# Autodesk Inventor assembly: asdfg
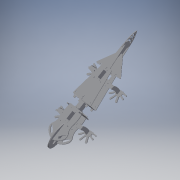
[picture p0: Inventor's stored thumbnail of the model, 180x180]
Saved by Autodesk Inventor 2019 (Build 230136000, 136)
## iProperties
Created: 2020-02
Part Number: asdfg
Document SubType Name: Assembly
Designer: shivu
Author: shivu
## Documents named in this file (10)
- C:\Users\shivu\Desktop\exploration\asdfg.iam
- C:\Users\shivu\Desktop\exploration\connector.ipt
- C:\Users\shivu\Downloads\11.ipt
- C:\Users\shivu\Desktop\exploration\final_upper.ipt
- C:\Users\shivu\Desktop\end part.iam
- C:\Users\shivu\Desktop\exploration\face.ipt
- C:\Users\shivu\Desktop\exploration\head upper.ipt
- C:\Users\shivu\Desktop\exploration\part99.ipt
- C:\Users\shivu\Desktop\exploration\part1000.ipt
- C:\Users\shivu\Desktop\exploration\servo.ipt
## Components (14 placed, 9 different names)
1. 11:1 — Rigid:16, Rigid:17, Rigid:26
2. connector:1 — Rotational:1, Cylindrical:1
3. final_upper:1 — Rigid:17, Rotational:1, Rigid:24
4. final_upper:2 — Rigid:16
5. end part:1 [sub-assembly] — Cylindrical:1
6. part99:1 — Rotational:3, Rigid:27, Rigid:28
7. part1000:2 — Rotational:2
8. servo:3 — Rigid:26, Rotational:3
9. servo:4 — Rigid:24, Rotational:2
10. head upper:1 — Rigid:27, Rigid:29, Rigid:30
11. head upper:2 — Rigid:28
12. face:1 — Rigid:29
13. servo:5 — Rigid:30, Rigid:31
14. part1000:3 — Rigid:31
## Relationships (13: WeldJoint 9, RevoluteJoint 3, CylindricalJoint 1)
- Rigid:16 [WeldJoint]: 11:1 ↔ final_upper:2
- Rigid:17 [WeldJoint]: 11:1 ↔ final_upper:1
- Rotational:1 [RevoluteJoint]: connector:1 ↔ final_upper:1
- Cylindrical:1: connector:1 ↔ end part:1
- Rigid:24 [WeldJoint]: final_upper:1 ↔ servo:4
- Rotational:2 [RevoluteJoint]: part1000:2 ↔ servo:4
- Rigid:26 [WeldJoint]: 11:1 ↔ servo:3
- Rotational:3 [RevoluteJoint]: part99:1 ↔ servo:3
- Rigid:27 [WeldJoint]: part99:1 ↔ head upper:1
- Rigid:28 [WeldJoint]: part99:1 ↔ head upper:2
- Rigid:29 [WeldJoint]: head upper:1 ↔ face:1
- Rigid:30 [WeldJoint]: head upper:1 ↔ servo:5
- Rigid:31 [WeldJoint]: servo:5 ↔ part1000:3
